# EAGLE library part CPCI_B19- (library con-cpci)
Compact PCI B 19 Source: www.erni.com
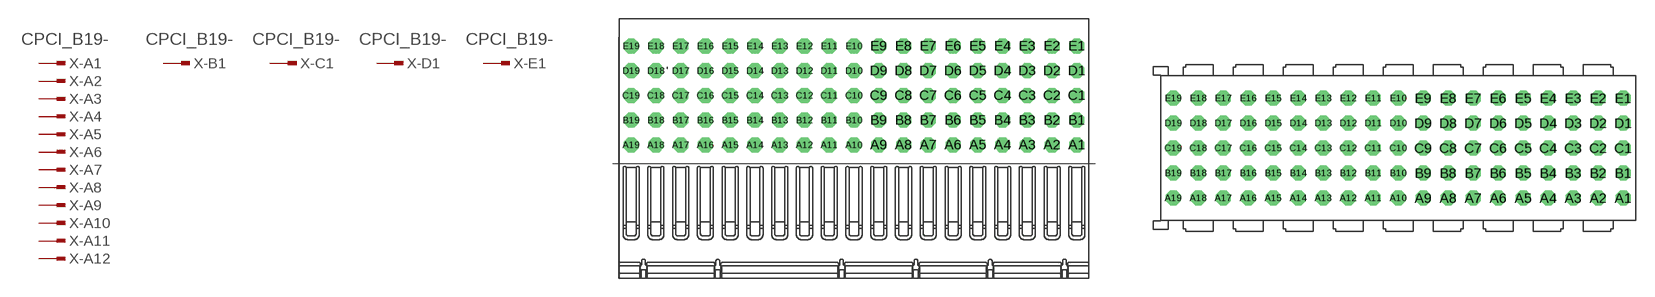
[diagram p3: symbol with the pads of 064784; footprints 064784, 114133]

Designator prefix X; gates -A1=PINV -B1=PINV -C1=PINV -D1=PINV -E1=PINV -A2=PIN -A3=PIN -A4=PIN -A5=PIN -A6=PIN -A7=PIN -A8=PIN -A9=PIN -A10=PIN -A11=PIN -A12=PIN -A13=PIN -A14=PIN -A15=PIN -A16=PIN -A17=PIN -A18=PIN -A19=PIN -B2=PIN -B3=PIN -B4=PIN -B5=PIN -B6=PIN -B7=PIN -B8=PIN -B9=PIN -B10=PIN -B11=PIN -B12=PIN -B13=PIN -B14=PIN -B15=PIN -B16=PIN -B17=PIN -B18=PIN -B19=PIN -C2=PIN -C3=PIN -C4=PIN -C5=PIN -C6=PIN -C7=PIN -C8=PIN -C9=PIN -C10=PIN -C11=PIN -C12=PIN -C13=PIN -C14=PIN -C15=PIN -C16=PIN -C17=PIN -C18=PIN -C19=PIN -D2=PIN -D3=PIN -D4=PIN -D5=PIN -D6=PIN -D7=PIN -D8=PIN -D9=PIN -D10=PIN -D11=PIN -D12=PIN -D13=PIN -D14=PIN -D15=PIN -D16=PIN -D17=PIN -D18=PIN -D19=PIN -E2=PIN -E3=PIN -E4=PIN -E5=PIN -E6=PIN -E7=PIN -E8=PIN -E9=PIN -E10=PIN -E11=PIN -E12=PIN -E13=PIN -E14=PIN -E15=PIN -E16=PIN -E17=PIN -E18=PIN -E19=PIN

## CPCI_B19-064784  [064784]
A1  -A1:1  in
A2  -A2:1  in
A3  -A3:1  in
A4  -A4:1  in
A5  -A5:1  in
A6  -A6:1  in
A7  -A7:1  in
A8  -A8:1  in
A9  -A9:1  in
A10  -A10:1  in
A11  -A11:1  in
A12  -A12:1  in
A13  -A13:1  in
A14  -A14:1  in
A15  -A15:1  in
A16  -A16:1  in
A17  -A17:1  in
A18  -A18:1  in
A19  -A19:1  in
B1  -B1:1  in
B2  -B2:1  in
B3  -B3:1  in
B4  -B4:1  in
B5  -B5:1  in
B6  -B6:1  in
B7  -B7:1  in
B8  -B8:1  in
B9  -B9:1  in
B10  -B10:1  in
B11  -B11:1  in
B12  -B12:1  in
B13  -B13:1  in
B14  -B14:1  in
B15  -B15:1  in
B16  -B16:1  in
B17  -B17:1  in
B18  -B18:1  in
B19  -B19:1  in
C1  -C1:1  in
C2  -C2:1  in
C3  -C3:1  in
C4  -C4:1  in
C5  -C5:1  in
C6  -C6:1  in
C7  -C7:1  in
C8  -C8:1  in
C9  -C9:1  in
C10  -C10:1  in
C11  -C11:1  in
C12  -C12:1  in
C13  -C13:1  in
C14  -C14:1  in
C15  -C15:1  in
C16  -C16:1  in
C17  -C17:1  in
C18  -C18:1  in
C19  -C19:1  in
D1  -D1:1  in
D2  -D2:1  in
D3  -D3:1  in
D4  -D4:1  in
D5  -D5:1  in
D6  -D6:1  in
D7  -D7:1  in
D8  -D8:1  in
D9  -D9:1  in
D10  -D10:1  in
D11  -D11:1  in
D12  -D12:1  in
D13  -D13:1  in
D14  -D14:1  in
D15  -D15:1  in
D16  -D16:1  in
D17  -D17:1  in
D18  -D18:1  in
D19  -D19:1  in
E1  -E1:1  in
E2  -E2:1  in
E3  -E3:1  in
E4  -E4:1  in
E5  -E5:1  in
E6  -E6:1  in
E7  -E7:1  in
E8  -E8:1  in
E9  -E9:1  in
E10  -E10:1  in
E11  -E11:1  in
E12  -E12:1  in
E13  -E13:1  in
E14  -E14:1  in
E15  -E15:1  in
E16  -E16:1  in
E17  -E17:1  in
E18  -E18:1  in
E19  -E19:1  in

## CPCI_B19-114133  [114133]
Pads as for 064784

## CPCI_B19-914794  [914794]
Pads as for 064784

## Footprint 064784 (pad centres in mm)
ERmet Federleiste B 19 / ERmet Female Type B 19 Source: http://www.erni.com/DB/PDF-Drawing/ERmet/064784.pdf
drill 0.7 pad 1.016 octagon: A1 18,1.5; A2 16,1.5; A3 14,1.5; A4 12,1.5; A5 10,1.5; A6 8,1.5; A7 6,1.5; A8 4,1.5; A9 2,1.5; A10 0,1.5; A11 -2,1.5; A12 -4,1.5; A13 -6,1.5; A14 -8,1.5; A15 -10,1.5; A16 -12,1.5; A17 -14,1.5; A18 -16,1.5; A19 -18,1.5; B1 18,3.5; B2 16,3.5; B3 14,3.5; B4 12,3.5; B5 10,3.5; B6 8,3.5; B7 6,3.5; B8 4,3.5; B9 2,3.5; B10 0,3.5; B11 -2,3.5; B12 -4,3.5; B13 -6,3.5; B14 -8,3.5; B15 -10,3.5; B16 -12,3.5; B17 -14,3.5; B18 -16,3.5; B19 -18,3.5; C1 18,5.5; C2 16,5.5; C3 14,5.5; C4 12,5.5; C5 10,5.5; C6 8,5.5; C7 6,5.5; C8 4,5.5; C9 2,5.5; C10 0,5.5; C11 -2,5.5; C12 -4,5.5; C13 -6,5.5; C14 -8,5.5; C15 -10,5.5; C16 -12,5.5; C17 -14,5.5; C18 -16,5.5; C19 -18,5.5; D1 18,7.5; D2 16,7.5; D3 14,7.5; D4 12,7.5; D5 10,7.5; D6 8,7.5; D7 6,7.5; D8 4,7.5; D9 2,7.5; D10 0,7.5; D11 -2,7.5; D12 -4,7.5; D13 -6,7.5; D14 -8,7.5; D15 -10,7.5; D16 -12,7.5; D17 -14,7.5; D18 -16,7.5; D19 -18,7.5; E1 18,9.5; E2 16,9.5; E3 14,9.5; E4 12,9.5; E5 10,9.5; E6 8,9.5; E7 6,9.5; E8 4,9.5; E9 2,9.5; E10 0,9.5; E11 -2,9.5; E12 -4,9.5; E13 -6,9.5; E14 -8,9.5; E15 -10,9.5; E16 -12,9.5; E17 -14,9.5; E18 -16,9.5; E19 -18,9.5

## Footprint 114133 (pad centres in mm)
ERmet-FS Federleiste B19 / ERmet-Female Straight Type B19 Source: http://www.erni.com/DB/PDF-Drawing/ERmet/114133.pdf
drill 0.7 pad 1.016 octagon: A1 18,-5; A2 16,-5; A3 14,-5; A4 12,-5; A5 10,-5; A6 8,-5; A7 6,-5; A8 4,-5; A9 2,-5; A10 0,-5; A11 -2,-5; A12 -4,-5; A13 -6,-5; A14 -8,-5; A15 -10,-5; A16 -12,-5; A17 -14,-5; A18 -16,-5; A19 -18,-5; B1 18,-3; B2 16,-3; B3 14,-3; B4 12,-3; B5 10,-3; B6 8,-3; B7 6,-3; B8 4,-3; B9 2,-3; B10 0,-3; B11 -2,-3; B12 -4,-3; B13 -6,-3; B14 -8,-3; B15 -10,-3; B16 -12,-3; B17 -14,-3; B18 -16,-3; B19 -18,-3; C1 18,-1; C2 16,-1; C3 14,-1; C4 12,-1; C5 10,-1; C6 8,-1; C7 6,-1; C8 4,-1; C9 2,-1; C10 0,-1; C11 -2,-1; C12 -4,-1; C13 -6,-1; C14 -8,-1; C15 -10,-1; C16 -12,-1; C17 -14,-1; C18 -16,-1; C19 -18,-1; D1 18,1; D2 16,1; D3 14,1; D4 12,1; D5 10,1; D6 8,1; D7 6,1; D8 4,1; D9 2,1; D10 0,1; D11 -2,1; D12 -4,1; D13 -6,1; D14 -8,1; D15 -10,1; D16 -12,1; D17 -14,1; D18 -16,1; D19 -18,1; E1 18,3; E2 16,3; E3 14,3; E4 12,3; E5 10,3; E6 8,3; E7 6,3; E8 4,3; E9 2,3; E10 0,3; E11 -2,3; E12 -4,3; E13 -6,3; E14 -8,3; E15 -10,3; E16 -12,3; E17 -14,3; E18 -16,3; E19 -18,3

## Footprint 914794 (pad centres in mm)
ERmet Federleiste B 19 / ERmet Female Type B 19 Source: http://www.erni.com/DB/PDF-Drawing/ERmet/914794i.pdf
drill 0.7 pad 1.016 octagon: A1 2.5,-64; A2 0.5,-64; A3 -1.5,-64; A4 -3.5,-64; A5 -5.5,-64; A6 -7.5,-64; A7 -9.5,-64; A8 -11.5,-64; A9 -13.5,-64; A10 -15.5,-64; A11 -17.5,-64; A12 -19.5,-64; A13 -21.5,-64; A14 -23.5,-64; A15 -25.5,-64; A16 -27.5,-64; A17 -29.5,-64; A18 -31.5,-64; A19 -33.5,-64; B1 2.5,-62; B2 0.5,-62; B3 -1.5,-62; B4 -3.5,-62; B5 -5.5,-62; B6 -7.5,-62; B7 -9.5,-62; B8 -11.5,-62; B9 -13.5,-62; B10 -15.5,-62; B11 -17.5,-62; B12 -19.5,-62; B13 -21.5,-62; B14 -23.5,-62; B15 -25.5,-62; B16 -27.5,-62; B17 -29.5,-62; B18 -31.5,-62; B19 -33.5,-62; C1 2.5,-60; C2 0.5,-60; C3 -1.5,-60; C4 -3.5,-60; C5 -5.5,-60; C6 -7.5,-60; C7 -9.5,-60; C8 -11.5,-60; C9 -13.5,-60; C10 -15.5,-60; C11 -17.5,-60; C12 -19.5,-60; C13 -21.5,-60; C14 -23.5,-60; C15 -25.5,-60; C16 -27.5,-60; C17 -29.5,-60; C18 -31.5,-60; C19 -33.5,-60; D1 2.5,-58; D2 0.5,-58; D3 -1.5,-58; D4 -3.5,-58; D5 -5.5,-58; D6 -7.5,-58; D7 -9.5,-58; D8 -11.5,-58; D9 -13.5,-58; D10 -15.5,-58; D11 -17.5,-58; D12 -19.5,-58; D13 -21.5,-58; D14 -23.5,-58; D15 -25.5,-58; D16 -27.5,-58; D17 -29.5,-58; D18 -31.5,-58; D19 -33.5,-58; E1 2.5,-56; E2 0.5,-56; E3 -1.5,-56; E4 -3.5,-56; E5 -5.5,-56; E6 -7.5,-56; E7 -9.5,-56; E8 -11.5,-56; E9 -13.5,-56; E10 -15.5,-56; E11 -17.5,-56; E12 -19.5,-56; E13 -21.5,-56; E14 -23.5,-56; E15 -25.5,-56; E16 -27.5,-56; E17 -29.5,-56; E18 -31.5,-56; E19 -33.5,-56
